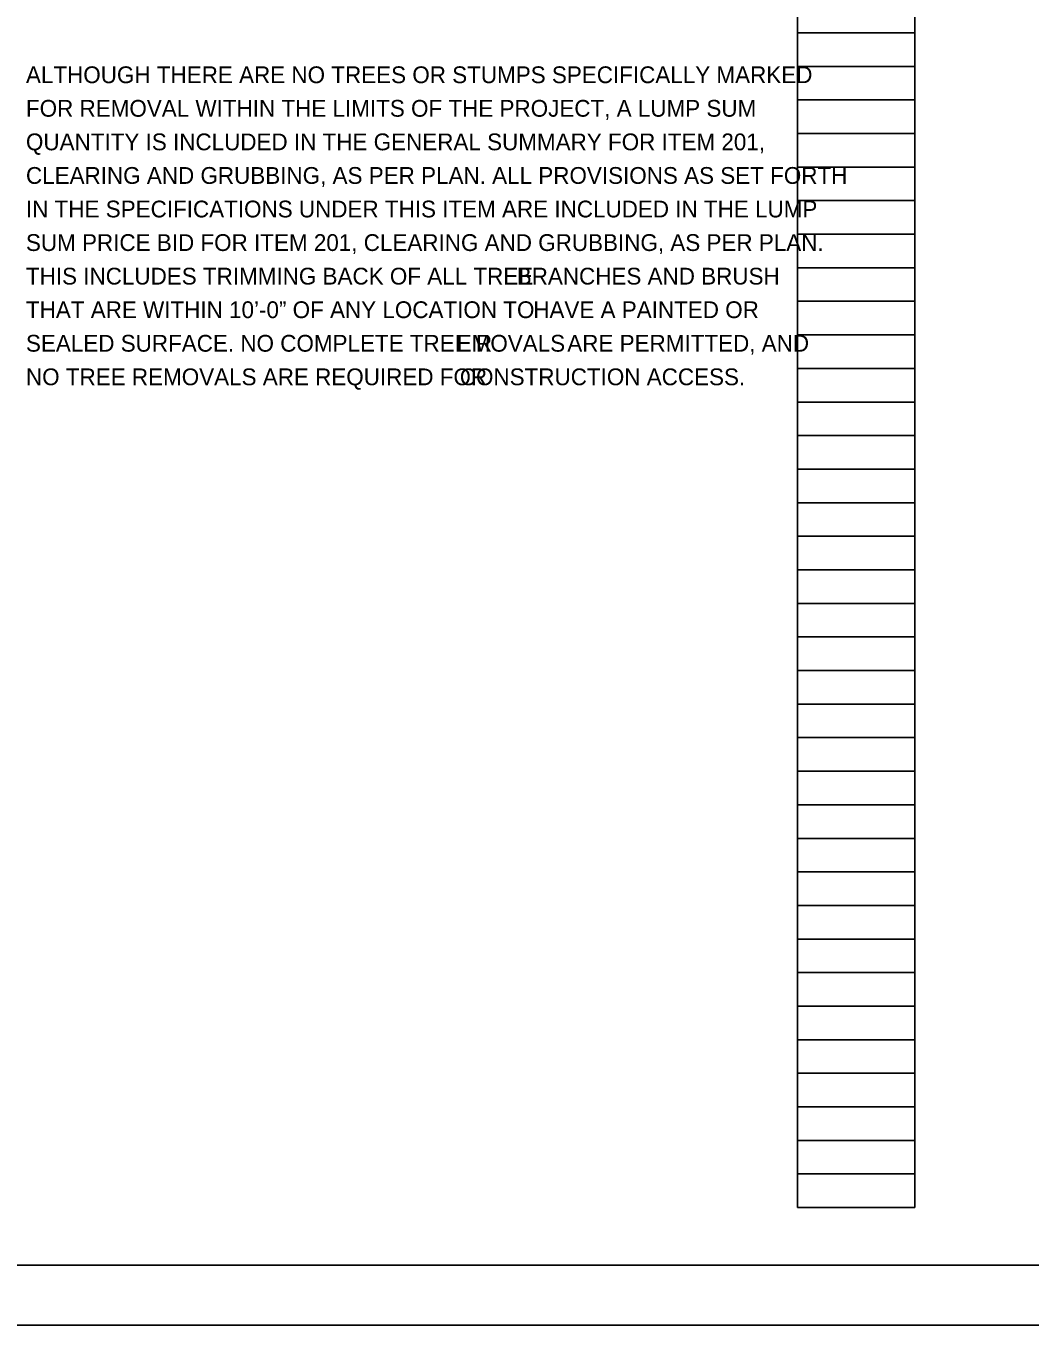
# Model space of a CAD drawing. Extents: x 0 to 34, y 0 to 25.2.
# Drawn here: x 17.24 to 25.62, y 0 to 10.84 of the extents above; entities that cross this region are included whole.
import ezdxf

# ---------------------------------------------------------------- set-up
doc = ezdxf.new("R2010")
doc.units = 0
for name, color, linetype in [('SH_Border', 7, 'Continuous'), ('SH_Cut_Line', 7, 'Continuous'), ('SH_Data', 7, 'Continuous'), ('SH_Text', 7, 'Continuous')]:
    doc.layers.add(name, color=color, linetype=linetype)

msp = doc.modelspace()

# ---------------------------------------------------------------- linework, layer by layer
at = {"layer": 'SH_Border'}
msp.add_lwpolyline([(1.5, 21.5), (33.5, 21.5), (33.5, 0.5), (1.5, 0.5)], close=True, dxfattribs=at)
at = {"layer": 'SH_Cut_Line'}
msp.add_lwpolyline([(0, 0), (34, 0), (34, 22), (0, 22)], close=True, dxfattribs=at)
at = {"layer": 'SH_Data'}
for p, q in [((23.68, 0.98), (23.68, 21.14)), ((24.66, 0.98), (24.66, 21.14)), ((23.68, 10.78), (24.66, 10.78)), ((23.68, 10.5), (24.66, 10.5)), ((23.68, 10.22), (24.66, 10.22)), ((23.68, 9.94), (24.66, 9.94)), ((23.68, 9.66), (24.66, 9.66)), ((23.68, 9.38), (24.66, 9.38)), ((23.68, 9.1), (24.66, 9.1)), ((23.68, 8.82), (24.66, 8.82)), ((23.68, 8.54), (24.66, 8.54)), ((23.68, 8.26), (24.66, 8.26)), ((23.68, 7.98), (24.66, 7.98)), ((23.68, 7.7), (24.66, 7.7)), ((23.68, 7.42), (24.66, 7.42)), ((23.68, 7.14), (24.66, 7.14)), ((23.68, 6.86), (24.66, 6.86)), ((23.68, 6.58), (24.66, 6.58)), ((23.68, 6.3), (24.66, 6.3)), ((23.68, 6.02), (24.66, 6.02)), ((23.68, 5.74), (24.66, 5.74)), ((23.68, 5.46), (24.66, 5.46)), ((23.68, 5.18), (24.66, 5.18)), ((23.68, 4.9), (24.66, 4.9)), ((23.68, 4.62), (24.66, 4.62)), ((23.68, 4.34), (24.66, 4.34)), ((23.68, 4.06), (24.66, 4.06)), ((23.68, 3.78), (24.66, 3.78)), ((23.68, 3.5), (24.66, 3.5)), ((23.68, 3.22), (24.66, 3.22)), ((23.68, 2.94), (24.66, 2.94)), ((23.68, 2.66), (24.66, 2.66)), ((23.68, 2.38), (24.66, 2.38)), ((23.68, 2.1), (24.66, 2.1)), ((23.68, 1.82), (24.66, 1.82)), ((23.68, 1.54), (24.66, 1.54)), ((23.68, 1.26), (24.66, 1.26)), ((23.68, 0.98), (24.66, 0.98))]:
    msp.add_line(p, q, dxfattribs=at)

# ---------------------------------------------------------------- texts
at = {"layer": 'SH_Text'}
for s, p in [('ALTHOUGH THERE ARE NO TREES OR STUMPS SPECIFICALLY MARKED ', (17.24, 10.36)), ('FOR REMOVAL WITHIN THE LIMITS OF THE PROJECT, A LUMP SUM ', (17.24, 10.08)), ('QUANTITY IS INCLUDED IN THE GENERAL SUMMARY FOR ITEM 201, ', (17.24, 9.8)), ('CLEARING AND GRUBBING, AS PER PLAN. ALL PROVISIONS AS SET FORTH ', (17.24, 9.52)), ('IN THE SPECIFICATIONS UNDER THIS ITEM ARE INCLUDED IN THE LUMP ', (17.24, 9.24)), ('SUM PRICE BID FOR ITEM 201, CLEARING AND GRUBBING, AS PER PLAN. ', (17.24, 8.96)), ('THIS INCLUDES TRIMMING BACK OF ALL TREE ', (17.24, 8.68)), ('BRANCHES AND BRUSH ', (21.336, 8.68)), ('THAT ARE WITHIN 10’-0” OF ANY LOCATION TO', (17.24, 8.4)), ('HAVE A PAINTED OR ', (21.474, 8.4)), ('SEALED SURFACE. NO COMPLETE TREE R', (17.24, 8.12)), ('EMOVALS ', (20.835, 8.12)), ('ARE PERMITTED, AND ', (21.758, 8.12)), ('NO TREE REMOVALS ARE REQUIRED FOR', (17.24, 7.84)), ('CONSTRUCTION ACCESS.', (20.861, 7.84))]:
    msp.add_text(s, height=0.14, dxfattribs=at).set_placement(p)

doc.saveas('drawing.dxf')
